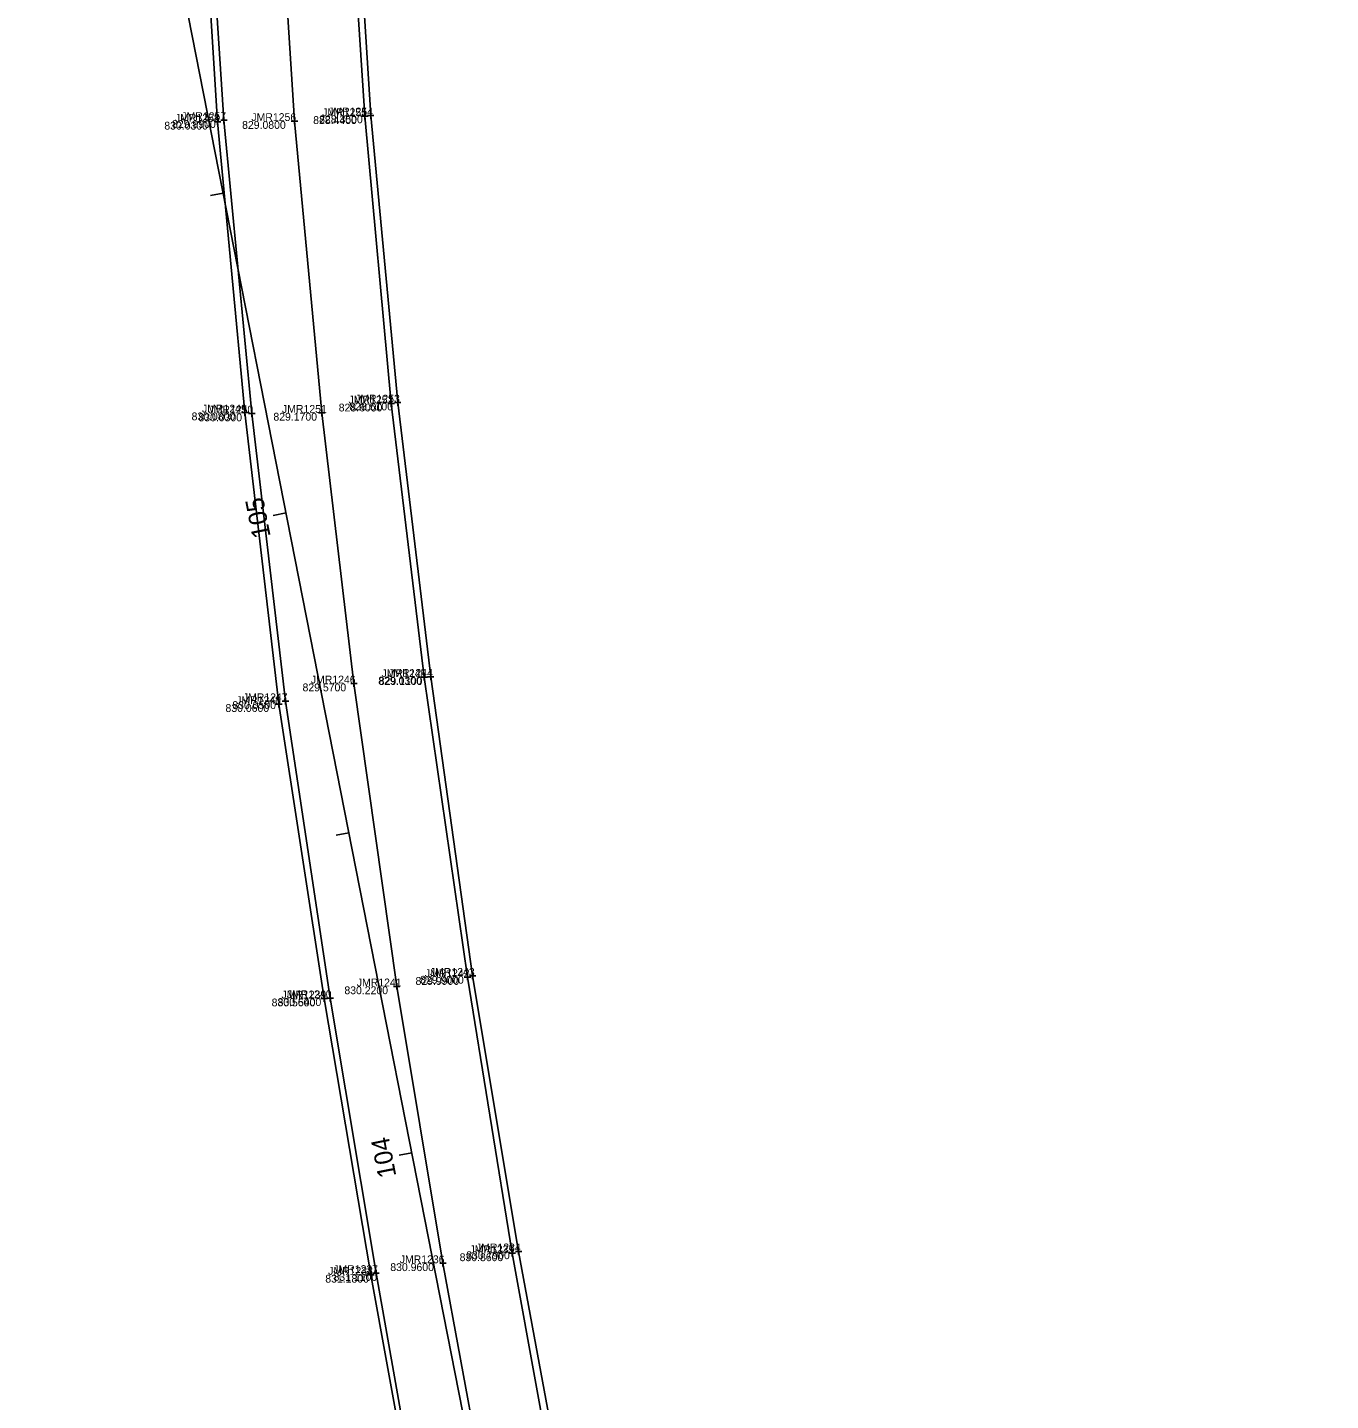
# Model space of a CAD drawing. Extents: x 1800057 to 1804439, y 483822 to 495007.
# Drawn here: x 1800130.2 to 1800330.1, y 493404.4 to 493615 of the extents above; entities that cross this region are included whole.
import ezdxf

# ---------------------------------------------------------------- set-up
doc = ezdxf.new("R2010")
doc.units = 0
for name, color, linetype in [('PV_X_EOP', 7, 'Continuous'), ('PV_X_Shoulder', 7, 'Continuous'), ('SV_X_Center_of_Pavt', 7, 'Continuous'), ('SV_X_CL_Survey_20', 7, 'Continuous'), ('SV_X_Shot_Marker', 7, 'Continuous'), ('SV_X_Text_Elevation', 7, 'Continuous'), ('SV_X_Text_Name', 7, 'Continuous')]:
    doc.layers.add(name, color=color, linetype=linetype)

msp = doc.modelspace()

# ---------------------------------------------------------------- linework, layer by layer
at = {"layer": 'PV_X_EOP'}
for points in [[(1800479.55, 492023.06), (1800449.85, 492176.97), (1800392.6, 492464.18), (1800311.54, 492873.87), (1800256.42, 493152.44), (1800212.54, 493383.09), (1800204.6, 493426.98), (1800197.72, 493469.35), (1800191.09, 493515.34), (1800186.01, 493557.29), (1800181.98, 493601.37), (1800178.73, 493651.43), (1800177.31, 493705.12), (1800177.69, 493752.12), (1800181.3, 493811.81)], [(1800458.51, 492019.19), (1800428.97, 492172.53), (1800371.73, 492460.04), (1800290.68, 492869.75), (1800235.42, 493149.26), (1800191.6, 493379.4), (1800183.7, 493423.96), (1800176.66, 493466.11), (1800169.82, 493511.65), (1800164.64, 493555.78), (1800160.38, 493600.77), (1800157.14, 493650.25), (1800154.83, 493705.12), (1800153.18, 493730.96), (1800152.82, 493734.69), (1800151.9, 493744.32), (1800151.68, 493749.1), (1800147.88, 493752.15), (1800140.39, 493754.62), (1800133.87, 493755.56), (1800130.23, 493754.97)]]:
    msp.add_lwpolyline(points, dxfattribs=at)
at = {"layer": 'PV_X_Shoulder'}
for points in [[(1800480.74, 492023.27), (1800451.07, 492177.26), (1800394.03, 492464.67), (1800312.92, 492873.97), (1800257.77, 493152.69), (1800213.69, 493383.34), (1800205.58, 493427.28), (1800198.52, 493469.53), (1800192.09, 493515.4), (1800187.03, 493557.46), (1800182.89, 493601.49), (1800179.75, 493651.39), (1800178.29, 493704.91), (1800178.63, 493752.05), (1800182.99, 493811.57)], [(1800457.45, 492018.92), (1800428.43, 492172.5), (1800370.8, 492459.92), (1800289.79, 492869.77), (1800234.57, 493149.05), (1800190.93, 493379.44), (1800182.91, 493423.69), (1800175.76, 493466.05), (1800168.8, 493511.21), (1800163.57, 493555.93), (1800159.41, 493600.52), (1800156.25, 493650.35), (1800153.42, 493705.28), (1800152.47, 493730.76)]]:
    msp.add_lwpolyline(points, dxfattribs=at)
at = {"layer": 'SV_X_Center_of_Pavt'}
msp.add_lwpolyline([(1800469.01, 492021.22), (1800439.37, 492174.81), (1800382.15, 492462.11), (1800301, 492872.15), (1800245.93, 493151.03), (1800202.07, 493381.28), (1800193.97, 493425.46), (1800186.87, 493467.92), (1800180.32, 493514.37), (1800175.39, 493555.88), (1800171.19, 493600.63), (1800167.99, 493651.05), (1800166.49, 493705.44), (1800166.61, 493753.56)], dxfattribs=at)
at = {"layer": 'SV_X_CL_Survey_20'}
for p, q in [((1800325.88, 492747.04), (1800141.96, 493682.68)), ((1800325.88, 492747.04), (1800141.96, 493682.68)), ((1800160.26, 493589.59), (1800158.29, 493589.21)), ((1800169.9, 493540.53), (1800167.94, 493540.15)), ((1800179.54, 493491.47), (1800177.58, 493491.09)), ((1800189.19, 493442.41), (1800187.23, 493442.03))]:
    msp.add_line(p, q, dxfattribs=at)
at = {"layer": 'SV_X_Shot_Marker'}
for p, q in [((1800160.38, 493601.27), (1800160.38, 493600.27)), ((1800181.48, 493601.37), (1800182.48, 493601.37)), ((1800181.98, 493601.87), (1800181.98, 493600.87)), ((1800181.98, 493601.37), (1800181.98, 493601.37)), ((1800182.39, 493601.49), (1800183.39, 493601.49)), ((1800182.89, 493601.99), (1800182.89, 493600.99)), ((1800182.89, 493601.49), (1800182.89, 493601.49)), ((1800158.91, 493600.52), (1800159.91, 493600.52)), ((1800159.41, 493601.02), (1800159.41, 493600.02)), ((1800159.41, 493600.52), (1800159.41, 493600.52)), ((1800159.88, 493600.77), (1800160.88, 493600.77)), ((1800160.38, 493600.77), (1800160.38, 493600.77)), ((1800170.69, 493600.63), (1800171.69, 493600.63)), ((1800171.19, 493601.13), (1800171.19, 493600.13)), ((1800171.19, 493600.63), (1800171.19, 493600.63)), ((1800185.51, 493557.29), (1800186.51, 493557.29)), ((1800186.01, 493557.79), (1800186.01, 493556.79)), ((1800186.01, 493557.29), (1800186.01, 493557.29)), ((1800186.53, 493557.46), (1800187.53, 493557.46)), ((1800187.03, 493557.96), (1800187.03, 493556.96)), ((1800187.03, 493557.46), (1800187.03, 493557.46)), ((1800163.07, 493555.93), (1800164.07, 493555.93)), ((1800163.57, 493556.43), (1800163.57, 493555.43)), ((1800163.57, 493555.93), (1800163.57, 493555.93)), ((1800164.14, 493555.78), (1800165.14, 493555.78)), ((1800164.64, 493556.28), (1800164.64, 493555.28)), ((1800164.64, 493555.78), (1800164.64, 493555.78)), ((1800174.89, 493555.88), (1800175.89, 493555.88)), ((1800175.39, 493556.38), (1800175.39, 493555.38)), ((1800175.39, 493555.88), (1800175.39, 493555.88)), ((1800180.32, 493514.87), (1800180.32, 493513.87)), ((1800190.59, 493515.34), (1800191.59, 493515.34)), ((1800191.09, 493515.84), (1800191.09, 493514.84)), ((1800191.09, 493515.34), (1800191.09, 493515.34)), ((1800191.59, 493515.4), (1800192.59, 493515.4)), ((1800192.09, 493515.9), (1800192.09, 493514.9)), ((1800192.09, 493515.4), (1800192.09, 493515.4)), ((1800179.82, 493514.37), (1800180.82, 493514.37)), ((1800180.32, 493514.37), (1800180.32, 493514.37)), ((1800168.3, 493511.21), (1800169.3, 493511.21)), ((1800168.8, 493511.71), (1800168.8, 493510.71)), ((1800168.8, 493511.21), (1800168.8, 493511.21)), ((1800169.32, 493511.65), (1800170.32, 493511.65)), ((1800169.82, 493512.15), (1800169.82, 493511.15)), ((1800169.82, 493511.65), (1800169.82, 493511.65)), ((1800197.22, 493469.35), (1800198.22, 493469.35)), ((1800197.72, 493469.85), (1800197.72, 493468.85)), ((1800197.72, 493469.35), (1800197.72, 493469.35)), ((1800198.02, 493469.53), (1800199.02, 493469.53)), ((1800198.52, 493470.03), (1800198.52, 493469.03)), ((1800198.52, 493469.53), (1800198.52, 493469.53)), ((1800175.76, 493466.55), (1800175.76, 493465.55)), ((1800176.66, 493466.61), (1800176.66, 493465.61)), ((1800186.37, 493467.92), (1800187.37, 493467.92)), ((1800186.87, 493468.42), (1800186.87, 493467.42)), ((1800186.87, 493467.92), (1800186.87, 493467.92)), ((1800175.26, 493466.05), (1800176.26, 493466.05)), ((1800175.76, 493466.05), (1800175.76, 493466.05)), ((1800176.16, 493466.11), (1800177.16, 493466.11)), ((1800176.66, 493466.11), (1800176.66, 493466.11)), ((1800204.1, 493426.98), (1800205.1, 493426.98)), ((1800204.6, 493427.48), (1800204.6, 493426.48)), ((1800204.6, 493426.98), (1800204.6, 493426.98)), ((1800205.08, 493427.28), (1800206.08, 493427.28)), ((1800205.58, 493427.78), (1800205.58, 493426.78)), ((1800205.58, 493427.28), (1800205.58, 493427.28)), ((1800183.7, 493424.46), (1800183.7, 493423.46)), ((1800193.47, 493425.46), (1800194.47, 493425.46)), ((1800193.97, 493425.96), (1800193.97, 493424.96)), ((1800193.97, 493425.46), (1800193.97, 493425.46)), ((1800182.41, 493423.69), (1800183.41, 493423.69)), ((1800182.91, 493424.19), (1800182.91, 493423.19)), ((1800182.91, 493423.69), (1800182.91, 493423.69)), ((1800183.2, 493423.96), (1800184.2, 493423.96)), ((1800183.7, 493423.96), (1800183.7, 493423.96))]:
    msp.add_line(p, q, dxfattribs=at)

# ---------------------------------------------------------------- texts
at = {"layer": 'SV_X_CL_Survey_20'}
for s, p in [('105', (1800167.55, 493536.94)), ('104', (1800186.83, 493438.85))]:
    msp.add_text(s, height=2.8, rotation=101.1211, dxfattribs=at).set_placement(p)
at = {"layer": 'SV_X_Text_Elevation'}
for s, p in [('828.4400', (1800174.06, 493600.17)), ('828.3500', (1800174.98, 493600.29)), ('830.0300', (1800151.23, 493599.32)), ('829.9900', (1800152.42, 493599.57)), ('829.0800', (1800163.16, 493599.43)), ('828.6000', (1800177.98, 493556.09)), ('828.5100', (1800179.61, 493556.26)), ('830.0800', (1800155.41, 493554.73)), ('830.0300', (1800156.46, 493554.58)), ('829.1700', (1800167.96, 493554.68)), ('829.0300', (1800184.04, 493514.2)), ('829.1100', (1800184.12, 493514.14)), ('829.5700', (1800172.43, 493513.17)), ('830.0600', (1800160.61, 493510.01)), ('830.0500', (1800161.66, 493510.45)), ('829.9900', (1800189.76, 493468.15)), ('829.9000', (1800190.47, 493468.33)), ('830.2200', (1800178.85, 493466.72)), ('830.5600', (1800167.69, 493464.85)), ('830.5400', (1800168.61, 493464.91)), ('830.8600', (1800196.53, 493425.78)), ('830.7900', (1800197.53, 493426.08)), ('830.9600', (1800185.89, 493424.26)), ('831.1800', (1800175.92, 493422.49)), ('831.1100', (1800177.18, 493422.76))]:
    msp.add_text(s, height=1.2, dxfattribs=at).set_placement(p)
at = {"layer": 'SV_X_Text_Name'}
for s, p in [('JMR1258', (1800152.86, 493600.52)), ('JMR1257', (1800153.84, 493600.77)), ('JMR1256', (1800164.58, 493600.63)), ('JMR1255', (1800175.44, 493601.37)), ('JMR1254', (1800176.37, 493601.49)), ('JMR1249', (1800157.01, 493555.93)), ('JMR1250', (1800158, 493555.78)), ('JMR1251', (1800169.28, 493555.88)), ('JMR1252', (1800179.49, 493557.29)), ('JMR1253', (1800180.49, 493557.46)), ('JMR1246', (1800173.7, 493514.37)), ('JMR1245', (1800184.55, 493515.34)), ('JMR1244', (1800185.55, 493515.4)), ('JMR1247', (1800163.27, 493511.65)), ('JMR1248', (1800162.24, 493511.21)), ('JMR1243', (1800191.97, 493469.53)), ('JMR1241', (1800180.75, 493467.92)), ('JMR1242', (1800191.18, 493469.35)), ('JMR1239', (1800169.2, 493466.05)), ('JMR1240', (1800170.01, 493466.11)), ('JMR1236', (1800187.34, 493425.46)), ('JMR1235', (1800198.04, 493426.98)), ('JMR1234', (1800199.03, 493427.28)), ('JMR1238', (1800176.35, 493423.69)), ('JMR1237', (1800177.14, 493423.96))]:
    msp.add_text(s, height=1.2, dxfattribs=at).set_placement(p)

doc.saveas('drawing.dxf')
